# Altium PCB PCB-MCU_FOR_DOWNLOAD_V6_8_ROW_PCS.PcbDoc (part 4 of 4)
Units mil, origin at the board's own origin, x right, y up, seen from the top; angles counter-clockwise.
Board outline not stored, 4 copper layers (Top, GND1, GND2, Bottom), stack 35.4 mil thick; 280 components, 38 nets, 1144 pads, 944 vias.
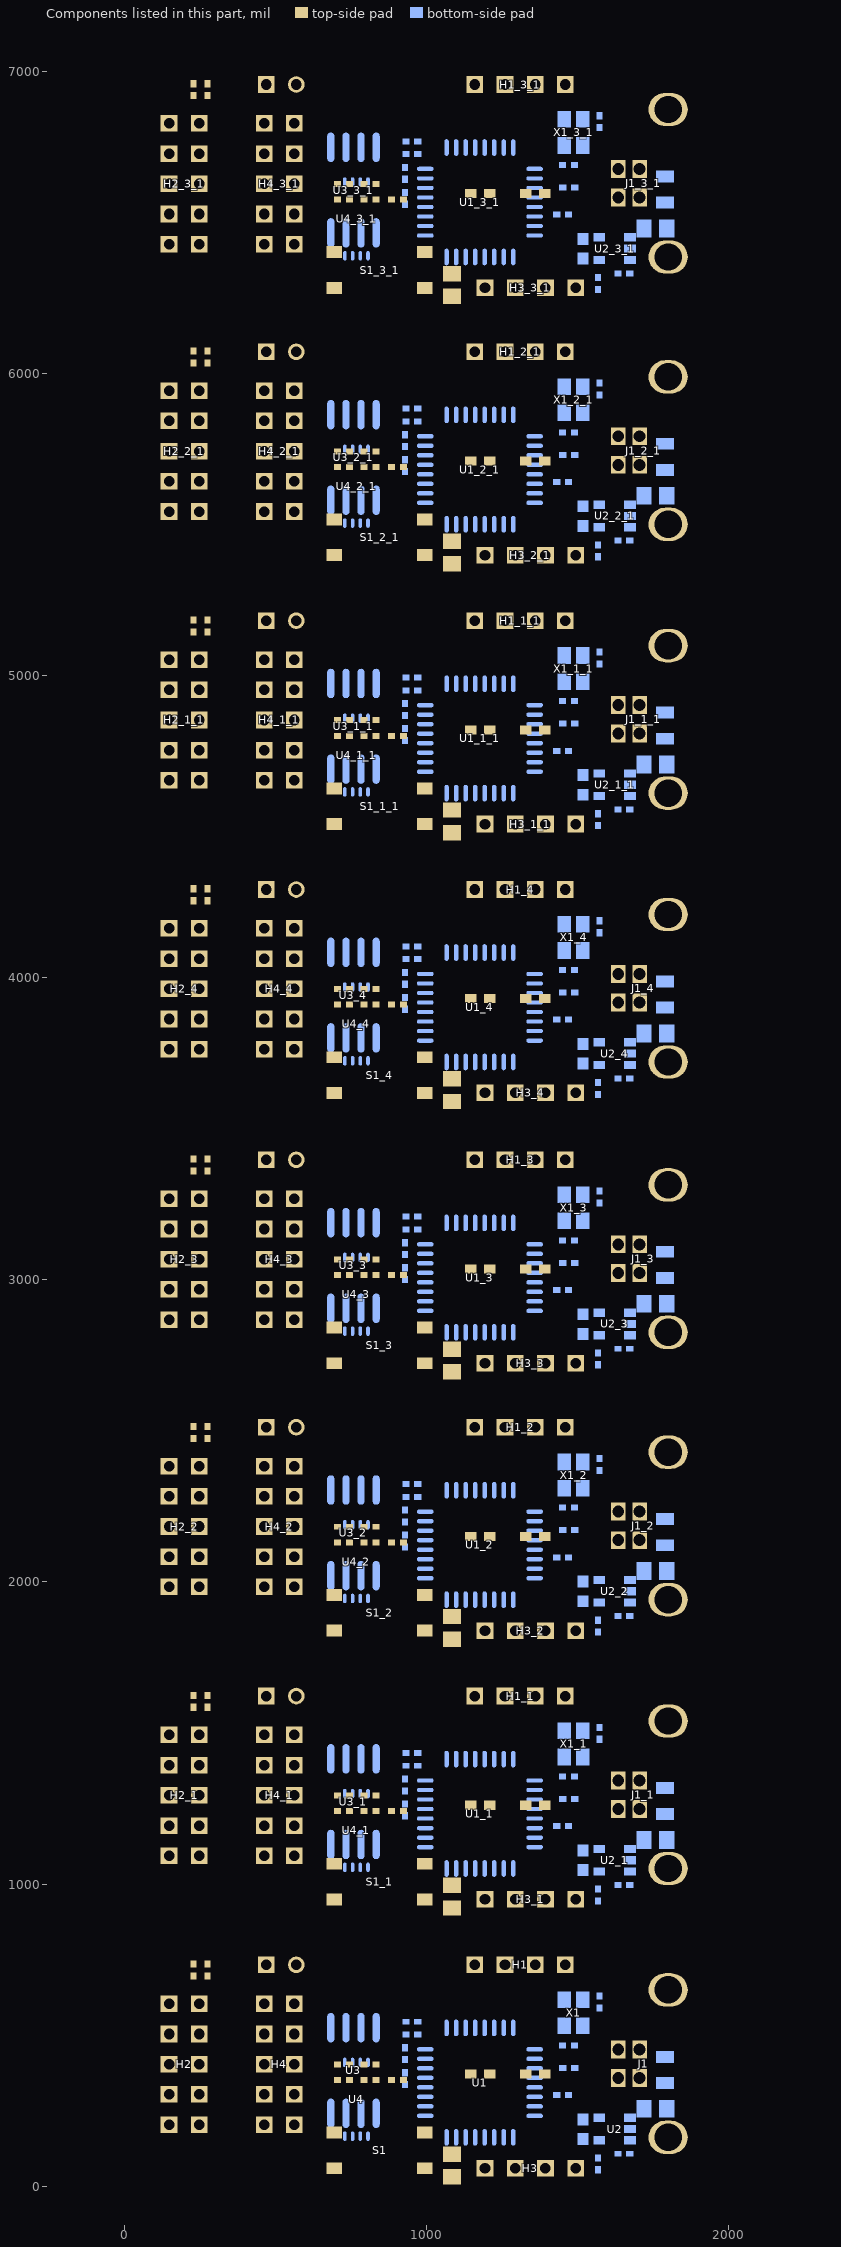
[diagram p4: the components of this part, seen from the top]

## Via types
v1: diameter 16/16/16/16 (per signal layer), hole 8, Top to Bottom, 936 vias
v2: diameter 55/55/55/55 (per signal layer), hole 37, Top to Bottom, 8 vias

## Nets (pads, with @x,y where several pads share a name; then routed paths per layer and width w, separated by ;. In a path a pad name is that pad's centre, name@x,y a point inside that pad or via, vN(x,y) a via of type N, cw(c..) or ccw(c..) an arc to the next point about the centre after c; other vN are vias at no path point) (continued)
copper on no net: (continued)
  other v1: 1723.62,917.17 1066.93,927.4 633.86,933.31 87.4,936.85 293.7,940 222.83,940.79 830.71,941.18 512.2,943.15 891.73,943.15 338.19,945.12 440.16,944.72 605.51,946.3 387.8,947.09 1934.25,949.45 61.81,958.11 772.83,957.72 1718.5,958.11 1917.32,1063.23 1896.46,1112.83 1261.81,1143.94 31.5,1189.21 403.54,1202.99 1909.45,1210.87 1120.08,1226.61 651.97,1235.28 118.11,1242.36 366.54,1249.84 297.24,1285.67 608.27,1291.18 1070.87,1307.32 1141.73,1309.29 1196.85,1327.01 685.04,1332.91 1913.39,1348.66 616.14,1380.16 25.2,1399.45 354.33,1403.78 1009.84,1407.72 1840.55,1415.59 1336.61,1417.56 1393.31,1419.53 1584.65,1425.43 1907.48,1441.18 1631.89,1458.9 1738.19,1464.8 1244.09,1478.58 874.02,1480.55 307.09,1482.52 1362.2,1492.36 1307.09,1496.3 1047.24,1510.08 991.34,1541.18 192.91,1541.57 1661.42,1553.39 572.83,1559.29 490.16,1561.26 1539.37,1578.98 419.29,1586.46 27.56,1587.64 371.26,1591.97 145.67,1611.65 337.4,1615.59 1098.82,1620.31 649.61,1623.07 921.26,1625.04 1635.83,1626.22 1742.13,1626.22 1909.45,1626.22 1828.74,1628.19 527.56,1668.35 761.81,1673.46 982.28,1673.86 1383.86,1673.46 1771.65,1673.46 1236.22,1677.4 1723.62,1807.17 1066.93,1817.4 633.86,1823.31 87.4,1826.85 293.7,1830 222.83,1830.79 830.71,1831.18 512.2,1833.15 891.73,1833.15 338.19,1835.12 440.16,1834.72 605.51,1836.3 387.8,1837.09 1934.25,1839.45 61.81,1848.11 772.83,1847.72 1718.5,1848.11 1917.32,1953.23 1896.46,2002.83 1261.81,2033.94 31.5,2079.21 403.54,2092.99 1909.45,2100.87 1120.08,2116.61 651.97,2125.28 118.11,2132.36 366.54,2139.84 297.24,2175.67 608.27,2181.18 1070.87,2197.32 1141.73,2199.29 1196.85,2217.01 685.04,2222.91 1913.39,2238.66 616.14,2270.16 25.2,2289.45 354.33,2293.78 1009.84,2297.72 1840.55,2305.59 1336.61,2307.56 1393.31,2309.53 1584.65,2315.43 1907.48,2331.18 1631.89,2348.9 1738.19,2354.8 1244.09,2368.58 874.02,2370.55 307.09,2372.52 1362.2,2382.36 1307.09,2386.3 1047.24,2400.08 991.34,2431.18 192.91,2431.57 1661.42,2443.39 572.83,2449.29 490.16,2451.26 1539.37,2468.98 419.29,2476.46 27.56,2477.64 371.26,2481.97 145.67,2501.65 337.4,2505.59 1098.82,2510.31 649.61,2513.07 921.26,2515.04 1635.83,2516.22 1742.13,2516.22 1909.45,2516.22 1828.74,2518.19 527.56,2558.35 761.81,2563.46 982.28,2563.86 1383.86,2563.46 1771.65,2563.46 1236.22,2567.4 1723.62,2692.17 1066.93,2702.4 633.86,2708.31 87.4,2711.85 293.7,2715 222.83,2715.79 830.71,2716.18 512.2,2718.15 891.73,2718.15 338.19,2720.12 440.16,2719.72 605.51,2721.3 387.8,2722.09 1934.25,2724.45 61.81,2733.11 772.83,2732.72 1718.5,2733.11 1917.32,2838.23 1896.46,2887.83 1261.81,2918.94 31.5,2964.21 403.54,2977.99 1909.45,2985.87 1120.08,3001.61 651.97,3010.28 118.11,3017.36 366.54,3024.84 297.24,3060.67 608.27,3066.18 1070.87,3082.32 1141.73,3084.29 1196.85,3102.01 685.04,3107.91 1913.39,3123.66 616.14,3155.16 25.2,3174.45 354.33,3178.78 1009.84,3182.72 1840.55,3190.59 1336.61,3192.56 1393.31,3194.53 1584.65,3200.43 1907.48,3216.18 1631.89,3233.9 1738.19,3239.8 1244.09,3253.58 874.02,3255.55 307.09,3257.52 1362.2,3267.36 1307.09,3271.3 1047.24,3285.08 991.34,3316.18 192.91,3316.57 1661.42,3328.39 572.83,3334.29 490.16,3336.26 1539.37,3353.98 419.29,3361.46 27.56,3362.64 371.26,3366.97 145.67,3386.65 337.4,3390.59 1098.82,3395.31 649.61,3398.07 921.26,3400.04 1635.83,3401.22 1742.13,3401.22 1909.45,3401.22 1828.74,3403.19 527.56,3443.35 761.81,3448.46 982.28,3448.86 1383.86,3448.46 1771.65,3448.46 1236.22,3452.4 1723.62,3587.17 1066.93,3597.4 633.86,3603.31 87.4,3606.85 293.7,3610 222.83,3610.79 830.71,3611.18 512.2,3613.15 891.73,3613.15 338.19,3615.12 440.16,3614.72 605.51,3616.3 387.8,3617.09 1934.25,3619.45 61.81,3628.11 772.83,3627.72 1718.5,3628.11 1917.32,3733.23 1896.46,3782.83 1261.81,3813.94 31.5,3859.21 403.54,3872.99 1909.45,3880.87 1120.08,3896.61 651.97,3905.28 118.11,3912.36 366.54,3919.84 297.24,3955.67 608.27,3961.18 1070.87,3977.32 1141.73,3979.29 1196.85,3997.01 685.04,4002.91 1913.39,4018.66 616.14,4050.16 25.2,4069.45 354.33,4073.78 1009.84,4077.72 1840.55,4085.59 1336.61,4087.56 1393.31,4089.53 1584.65,4095.43 1907.48,4111.18 1631.89,4128.9 1738.19,4134.8 1244.09,4148.58 874.02,4150.55 307.09,4152.52 1362.2,4162.36 1307.09,4166.3 1047.24,4180.08 991.34,4211.18 192.91,4211.57 1661.42,4223.39 572.83,4229.29 490.16,4231.26 1539.37,4248.98 419.29,4256.46 27.56,4257.64 371.26,4261.97 145.67,4281.65 337.4,4285.59 1098.82,4290.31 649.61,4293.07 921.26,4295.04 1635.83,4296.22 1742.13,4296.22 1909.45,4296.22 1828.74,4298.19 527.56,4338.35 761.81,4343.46 982.28,4343.86 1383.86,4343.46 1771.65,4343.46 1236.22,4347.4 1723.62,4477.17 1066.93,4487.4 633.86,4493.31 87.4,4496.85 293.7,4500 222.83,4500.79 830.71,4501.18 512.2,4503.15 891.73,4503.15 338.19,4505.12 440.16,4504.72 605.51,4506.3 387.8,4507.09 1934.25,4509.45 61.81,4518.11 772.83,4517.72 1718.5,4518.11 1917.32,4623.23 1896.46,4672.83 1261.81,4703.94 31.5,4749.21 403.54,4762.99 1909.45,4770.87 1120.08,4786.61 651.97,4795.28 118.11,4802.36 366.54,4809.84 297.24,4845.67 608.27,4851.18 1070.87,4867.32 1141.73,4869.29 1196.85,4887.01 685.04,4892.91 1913.39,4908.66 616.14,4940.16 25.2,4959.45 354.33,4963.78 1009.84,4967.72 1840.55,4975.59 1336.61,4977.56 1393.31,4979.53 1584.65,4985.43 1907.48,5001.18 1631.89,5018.9 1738.19,5024.8 1244.09,5038.58 874.02,5040.55 307.09,5042.52 1362.2,5052.36 1307.09,5056.3 1047.24,5070.08 991.34,5101.18 192.91,5101.57 1661.42,5113.39 572.83,5119.29 490.16,5121.26 1539.37,5138.98 419.29,5146.46 27.56,5147.64 371.26,5151.97 145.67,5171.65 337.4,5175.59 1098.82,5180.31 649.61,5183.07 921.26,5185.04 1635.83,5186.22 1742.13,5186.22 1909.45,5186.22 1828.74,5188.19 527.56,5228.35 761.81,5233.46 982.28,5233.86 1383.86,5233.46 1771.65,5233.46 1236.22,5237.4 1723.62,5367.17 1066.93,5377.4 633.86,5383.31 87.4,5386.85 293.7,5390 222.83,5390.79 830.71,5391.18 512.2,5393.15 891.73,5393.15 338.19,5395.12 440.16,5394.72 605.51,5396.3 387.8,5397.09 1934.25,5399.45 61.81,5408.11 772.83,5407.72 1718.5,5408.11 1917.32,5513.23 1896.46,5562.83 1261.81,5593.94 31.5,5639.21 403.54,5652.99 1909.45,5660.87 1120.08,5676.61 651.97,5685.28 118.11,5692.36 366.54,5699.84 297.24,5735.67 608.27,5741.18 1070.87,5757.32 1141.73,5759.29 1196.85,5777.01 685.04,5782.91 1913.39,5798.66 616.14,5830.16 25.2,5849.45 354.33,5853.78 1009.84,5857.72 1840.55,5865.59 1336.61,5867.56 1393.31,5869.53 1584.65,5875.43 1907.48,5891.18 1631.89,5908.9 1738.19,5914.8 1244.09,5928.58 874.02,5930.55 307.09,5932.52 1362.2,5942.36 1307.09,5946.3 1047.24,5960.08 991.34,5991.18 192.91,5991.57 1661.42,6003.39 572.83,6009.29 490.16,6011.26 1539.37,6028.98 419.29,6036.46 27.56,6037.64 371.26,6041.97 145.67,6061.65 337.4,6065.59 1098.82,6070.31 649.61,6073.07 921.26,6075.04 1635.83,6076.22 1742.13,6076.22 1909.45,6076.22 1828.74,6078.19 527.56,6118.35 761.81,6123.46 982.28,6123.86 1383.86,6123.46 1771.65,6123.46 1236.22,6127.4 1723.62,6252.17 1066.93,6262.4 633.86,6268.31 87.4,6271.85 293.7,6275 222.83,6275.79 830.71,6276.18 512.2,6278.15 891.73,6278.15 338.19,6280.12 440.16,6279.72 605.51,6281.3 387.8,6282.09 1934.25,6284.45 61.81,6293.11 772.83,6292.72 1718.5,6293.11 1917.32,6398.23 1896.46,6447.83 1261.81,6478.94 31.5,6524.21 403.54,6537.99 1909.45,6545.87 1120.08,6561.61 651.97,6570.28 118.11,6577.36 366.54,6584.84 297.24,6620.67 608.27,6626.18 1070.87,6642.32 1141.73,6644.29 1196.85,6662.01 685.04,6667.91 1913.39,6683.66 616.14,6715.16 25.2,6734.45 354.33,6738.78 1009.84,6742.72 1840.55,6750.59 1336.61,6752.56 1393.31,6754.53 1584.65,6760.43 1907.48,6776.18 1631.89,6793.9 1738.19,6799.8 1244.09,6813.58 874.02,6815.55 307.09,6817.52 1362.2,6827.36 1307.09,6831.3 1047.24,6845.08 991.34,6876.18 192.91,6876.57 1661.42,6888.39 572.83,6894.29 490.16,6896.26 1539.37,6913.98 419.29,6921.46 27.56,6922.64 371.26,6926.97 145.67,6946.65 337.4,6950.59 1098.82,6955.31 649.61,6958.07 921.26,6960.04 1635.83,6961.22 1742.13,6961.22 1909.45,6961.22 1828.74,6963.19 527.56,7003.35 761.81,7008.46 982.28,7008.86 1383.86,7008.46 1771.65,7008.46 1236.22,7012.4

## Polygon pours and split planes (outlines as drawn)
no net on Top "Top-GGND" (solid, remove dead copper, pour order 12): -3.15,3560 2215,3560 2215,4378.5 -3.15,4378.5
no net on Top "Top-GGND" (solid, remove dead copper, pour order 11): -3.15,4450 2215,4450 2215,5268.5 -3.15,5268.5
no net on Top "Top-GGND" (solid, remove dead copper, pour order 10): -3.15,5340 2215,5340 2215,6158.5 -3.15,6158.5
no net on Top "Top-GGND" (solid, remove dead copper, pour order 9): -3.15,6225 2215,6225 2215,7043.5 -3.15,7043.5
no net on Top "Top-GGND" (solid, remove dead copper, pour order 9): -3.15,2665 2215,2665 2215,3483.5 -3.15,3483.5
no net on Top "Top-GGND" (solid, remove dead copper, pour order 10): -3.15,1780 2215,1780 2215,2598.5 -3.15,2598.5
no net on Top "Top-GGND" (solid, remove dead copper, pour order 11): -3.15,890 2215,890 2215,1708.5 -3.15,1708.5
GGND on Top "Top-GGND" (solid, remove dead copper, pour order 12): -3.15,0 2215,0 2215,818.5 -3.15,818.5
no net on Bottom "Bottom-GGND" (solid, remove dead copper, pour order 16): -6.69,3560 2210,3560 2210,4370.24 -6.69,4370.24
no net on Bottom "Bottom-GGND" (solid, remove dead copper, pour order 15): -6.69,4450 2210,4450 2210,5260.24 -6.69,5260.24
no net on Bottom "Bottom-GGND" (solid, remove dead copper, pour order 14): -6.69,5340 2210,5340 2210,6150.24 -6.69,6150.24
no net on Bottom "Bottom-GGND" (solid, remove dead copper, pour order 13): -6.69,6225 2210,6225 2210,7035.24 -6.69,7035.24
no net on Bottom "Bottom-GGND" (solid, remove dead copper, pour order 13): -6.69,2665 2210,2665 2210,3475.24 -6.69,3475.24
no net on Bottom "Bottom-GGND" (solid, remove dead copper, pour order 14): -6.69,1780 2210,1780 2210,2590.24 -6.69,2590.24
no net on Bottom "Bottom-GGND" (solid, remove dead copper, pour order 15): -6.69,890 2210,890 2210,1700.24 -6.69,1700.24
GGND on Bottom "Bottom-GGND" (solid, remove dead copper, pour order 16): -6.69,0 2210,0 2210,810.24 -6.69,810.24

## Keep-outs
Keep-Out Layer:
  lines w10: 0,59.01 ccw(c56.63,56.63) 59.1,0 ; 0,59.01 0,325 -55,325 -135,325 -135,3143.54 -135,6703.54 -55,6703.54 0,6703.54 0,6973.03 cw(c57.94,6974.14) 59.06,7032.09 2160,7032.09 cw(c2157.3,6970.34) 2219.06,6973.03 2219.06,6284.06 cw(c2159.85,6284.26) 2159.95,6225.05 ; 0,748.03 cw(c57.94,749.14) 59.06,807.09 2160,807.09 cw(c2157.3,745.34) 2219.06,748.03 2219.06,59.06 cw(c2159.85,59.26) 2159.95,0.05 ; 0,750 0,475 -55,475 -55,1218.54 0,1218.54 0,949.01 ; 0,949.01 ccw(c56.63,946.63) 59.1,890 ; 0,1839.01 ccw(c56.63,1836.63) 59.1,1780 ; 0,1839.01 0,2108.54 -55,2108.54 -55,1368.54 0,1368.54 0,1638.03 cw(c57.94,1639.14) 59.06,1697.09 2160,1697.09 cw(c2157.3,1635.34) 2219.06,1638.03 2219.06,949.06 cw(c2159.85,949.26) 2159.95,890.05 ; 0,2724.01 ccw(c56.63,2721.63) 59.1,2665 ; 0,2724.01 0,2993.54 -55,2993.54 -55,2258.54 0,2258.54 0,2528.03 cw(c57.94,2529.14) 59.06,2587.09 2160,2587.09 cw(c2157.3,2525.34) 2219.06,2528.03 2219.06,1839.06 cw(c2159.85,1839.26) 2159.95,1780.05 ; 0,3619.01 ccw(c56.63,3616.63) 59.1,3560 ; 0,3619.01 0,3885 -55,3885 -55,3143.54 0,3143.54 0,3413.03 cw(c57.94,3414.14) 59.06,3472.09 2160,3472.09 cw(c2157.3,3410.34) 2219.06,3413.03 2219.06,2724.06 cw(c2159.85,2724.26) 2159.95,2665.05 ; 0,4308.03 cw(c57.94,4309.14) 59.06,4367.09 2160,4367.09 cw(c2157.3,4305.34) 2219.06,4308.03 2219.06,3619.06 cw(c2159.85,3619.26) 2159.95,3560.05 ; 0,4310 0,4035 -55,4035 -55,4778.54 0,4778.54 0,4509.01 ; 0,4509.01 ccw(c56.63,4506.63) 59.1,4450 ; 0,5399.01 ccw(c56.63,5396.63) 59.1,5340 ; 0,5399.01 0,5668.54 -55,5668.54 -55,4928.54 0,4928.54 0,5198.03 cw(c57.94,5199.14) 59.06,5257.09 2160,5257.09 cw(c2157.3,5195.34) 2219.06,5198.03 2219.06,4509.06 cw(c2159.85,4509.26) 2159.95,4450.05 ; 0,6284.01 ccw(c56.63,6281.63) 59.1,6225 ; 0,6284.01 0,6553.54 -55,6553.54 -55,5818.54 0,5818.54 0,6088.03 cw(c57.94,6089.14) 59.06,6147.09 2160,6147.09 cw(c2157.3,6085.34) 2219.06,6088.03 2219.06,5399.06 cw(c2159.85,5399.26) 2159.95,5340.05 ; 59.06,0 2160,0 ; 59.06,890 2160,890 ; 59.06,1780 2160,1780 ; 59.06,2665 2160,2665 ; 59.06,3560 2160,3560 ; 59.06,4450 2160,4450 ; 59.06,5340 2160,5340 ; 59.06,6225 2160,6225

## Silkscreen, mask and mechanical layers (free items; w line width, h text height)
Silkscreen Top:
  drawing of 232 lines, arcs and shapes, not listed
  text "VDD" at 627.95,6971.06 h25.59
  text "VCC" at 330.31,6969.09 h25.59
  text "深圳市集贤科技有限公司" at 1613.78,6967.52 h50
  text "1.0" at 1229.53,6841.54 h29.53
  text "0.7" at 1326.38,6841.93 h29.53
  text "1.1" at 1132.28,6840.75 h29.53
  text "0.6" at 1427.95,6840.75 h29.53
  text "WP" at 348.43,6804.92 h25.59 r90
  text "CS" at 405.91,6801.38 h25.59 r90
  text "CS" at 89.37,6799.02 h25.59 r90
  text "WP" at 657.09,6792.72 h25.59 r90
  text "HW SPI Jumpers" at 681.89,6773.82 h29.53
  text "Int:R7=R8=0R" at 704.33,6705.71 h29.53
  text "VPP" at 87.8,6699.8 h25.59 r90
  text "VPP" at 412.2,6697.05 h25.59 r90
  text "VCC" at 347.24,6693.11 h25.59 r90
  text "VCC" at 655.91,6680.91 h25.59 r90
  text "GND" at 89.37,6592.72 h25.59 r90
  text "GND" at 343.31,6591.54 h25.59 r90
  text "GND" at 405.51,6588.78 h25.59 r90
  text "GND" at 651.97,6579.33 h25.59 r90
  text "P2.4" at 88.58,6489.57 h25.59 r90
  text "P2.3" at 343.31,6487.2 h25.59 r90
  text "Ext:R9=R10=R13=0R" at 665.35,6478.15 h25.59
  text "POWER" at 1270.47,6440.75 h39.37
  text "MISO" at 649.21,6383.66 h25.59 r90
  text "MOSI" at 90.55,6379.33 h25.59 r90
  text "MISO" at 342.52,6377.36 h25.59 r90
  text "MOSI" at 406.69,6375.39 h25.59 r90
  text "VDD" at 1130.71,6345.47 h29.53
  text "C2D" at 1230.71,6346.26 h29.53
  text "CK" at 1374.41,6343.5 h29.53
  text "GND" at 1445.67,6344.29 h29.53
  text "SW" at 188.19,6265.16 h49.21 r90
  text "HW" at 505.51,6260.43 h49.21 r90
  text "SPI" at 269.29,6258.46 h49.21 r90
  text "MCU_FOR_DOWMLOAD_v1.0" at 1627.17,6254.92 h29.53
  text "SPI" at 590.16,6253.74 h49.21 r90
  text "VDD" at 627.95,6086.06 h25.59
  text "VCC" at 330.31,6084.09 h25.59
  text "深圳市集贤科技有限公司" at 1613.78,6082.52 h50
  text "1.0" at 1229.53,5956.54 h29.53
  text "0.7" at 1326.38,5956.93 h29.53
  text "1.1" at 1132.28,5955.75 h29.53
  text "0.6" at 1427.95,5955.75 h29.53
  text "WP" at 348.43,5919.92 h25.59 r90
  text "CS" at 405.91,5916.38 h25.59 r90
  text "CS" at 89.37,5914.02 h25.59 r90
  text "WP" at 657.09,5907.72 h25.59 r90
  text "HW SPI Jumpers" at 681.89,5888.82 h29.53
  text "Int:R7=R8=0R" at 704.33,5820.71 h29.53
  text "VPP" at 87.8,5814.8 h25.59 r90
  text "VPP" at 412.2,5812.05 h25.59 r90
  text "VCC" at 347.24,5808.11 h25.59 r90
  text "VCC" at 655.91,5795.91 h25.59 r90
  text "GND" at 89.37,5707.72 h25.59 r90
  text "GND" at 343.31,5706.54 h25.59 r90
  text "GND" at 405.51,5703.78 h25.59 r90
  text "GND" at 651.97,5694.33 h25.59 r90
  text "P2.4" at 88.58,5604.57 h25.59 r90
  text "P2.3" at 343.31,5602.2 h25.59 r90
  text "Ext:R9=R10=R13=0R" at 665.35,5593.15 h25.59
  text "POWER" at 1270.47,5555.75 h39.37
  text "MISO" at 649.21,5498.66 h25.59 r90
  text "MOSI" at 90.55,5494.33 h25.59 r90
  text "MISO" at 342.52,5492.36 h25.59 r90
  text "MOSI" at 406.69,5490.39 h25.59 r90
  text "VDD" at 1130.71,5460.47 h29.53
  text "C2D" at 1230.71,5461.26 h29.53
  text "CK" at 1374.41,5458.5 h29.53
  text "GND" at 1445.67,5459.29 h29.53
  text "SW" at 188.19,5380.16 h49.21 r90
  text "HW" at 505.51,5375.43 h49.21 r90
  text "SPI" at 269.29,5373.46 h49.21 r90
  text "MCU_FOR_DOWMLOAD_v1.0" at 1627.17,5369.92 h29.53
  text "SPI" at 590.16,5368.74 h49.21 r90
  text "VDD" at 627.95,5196.06 h25.59
  text "VCC" at 330.31,5194.09 h25.59
  text "深圳市集贤科技有限公司" at 1613.78,5192.52 h50
  text "1.0" at 1229.53,5066.54 h29.53
  text "0.7" at 1326.38,5066.93 h29.53
  text "1.1" at 1132.28,5065.75 h29.53
  text "0.6" at 1427.95,5065.75 h29.53
  text "WP" at 348.43,5029.92 h25.59 r90
  text "CS" at 405.91,5026.38 h25.59 r90
  text "CS" at 89.37,5024.02 h25.59 r90
  text "WP" at 657.09,5017.72 h25.59 r90
  text "HW SPI Jumpers" at 681.89,4998.82 h29.53
  text "Int:R7=R8=0R" at 704.33,4930.71 h29.53
  text "VPP" at 87.8,4924.8 h25.59 r90
  text "VPP" at 412.2,4922.05 h25.59 r90
  text "VCC" at 347.24,4918.11 h25.59 r90
  text "VCC" at 655.91,4905.91 h25.59 r90
  text "GND" at 89.37,4817.72 h25.59 r90
  text "GND" at 343.31,4816.54 h25.59 r90
  text "GND" at 405.51,4813.78 h25.59 r90
  text "GND" at 651.97,4804.33 h25.59 r90
  text "P2.4" at 88.58,4714.57 h25.59 r90
  text "P2.3" at 343.31,4712.2 h25.59 r90
  text "Ext:R9=R10=R13=0R" at 665.35,4703.15 h25.59
  text "POWER" at 1270.47,4665.75 h39.37
  text "MISO" at 649.21,4608.66 h25.59 r90
  text "MOSI" at 90.55,4604.33 h25.59 r90
  text "MISO" at 342.52,4602.36 h25.59 r90
  text "MOSI" at 406.69,4600.39 h25.59 r90
  text "VDD" at 1130.71,4570.47 h29.53
  text "C2D" at 1230.71,4571.26 h29.53
  text "CK" at 1374.41,4568.5 h29.53
  text "GND" at 1445.67,4569.29 h29.53
  text "SW" at 188.19,4490.16 h49.21 r90
  text "HW" at 505.51,4485.43 h49.21 r90
  text "SPI" at 269.29,4483.46 h49.21 r90
  text "MCU_FOR_DOWMLOAD_v1.0" at 1627.17,4479.92 h29.53
  text "SPI" at 590.16,4478.74 h49.21 r90
  text "VDD" at 627.95,4306.06 h25.59
  text "VCC" at 330.31,4304.09 h25.59
  text "深圳市集贤科技有限公司" at 1613.78,4302.52 h50
  text "1.0" at 1229.53,4176.54 h29.53
  text "0.7" at 1326.38,4176.93 h29.53
  text "1.1" at 1132.28,4175.75 h29.53
  text "0.6" at 1427.95,4175.75 h29.53
  text "WP" at 348.43,4139.92 h25.59 r90
  text "CS" at 405.91,4136.38 h25.59 r90
  text "CS" at 89.37,4134.02 h25.59 r90
  text "WP" at 657.09,4127.72 h25.59 r90
  text "HW SPI Jumpers" at 681.89,4108.82 h29.53
  text "Int:R7=R8=0R" at 704.33,4040.71 h29.53
  text "VPP" at 87.8,4034.8 h25.59 r90
  text "VPP" at 412.2,4032.05 h25.59 r90
  text "VCC" at 347.24,4028.11 h25.59 r90
  text "VCC" at 655.91,4015.91 h25.59 r90
  text "GND" at 89.37,3927.72 h25.59 r90
  text "GND" at 343.31,3926.54 h25.59 r90
  text "GND" at 405.51,3923.78 h25.59 r90
  text "GND" at 651.97,3914.33 h25.59 r90
  text "P2.4" at 88.58,3824.57 h25.59 r90
  text "P2.3" at 343.31,3822.2 h25.59 r90
  text "Ext:R9=R10=R13=0R" at 665.35,3813.15 h25.59
  text "POWER" at 1270.47,3775.75 h39.37
  text "MISO" at 649.21,3718.66 h25.59 r90
  text "MOSI" at 90.55,3714.33 h25.59 r90
  text "MISO" at 342.52,3712.36 h25.59 r90
  text "MOSI" at 406.69,3710.39 h25.59 r90
  text "VDD" at 1130.71,3680.47 h29.53
  text "C2D" at 1230.71,3681.26 h29.53
  text "CK" at 1374.41,3678.5 h29.53
  text "GND" at 1445.67,3679.29 h29.53
  text "SW" at 188.19,3600.16 h49.21 r90
  text "HW" at 505.51,3595.43 h49.21 r90
  text "SPI" at 269.29,3593.46 h49.21 r90
  text "MCU_FOR_DOWMLOAD_v1.0" at 1627.17,3589.92 h29.53
  text "SPI" at 590.16,3588.74 h49.21 r90
  text "VDD" at 627.95,3411.06 h25.59
  text "VCC" at 330.31,3409.09 h25.59
  text "深圳市集贤科技有限公司" at 1613.78,3407.52 h50
  text "1.0" at 1229.53,3281.54 h29.53
  text "0.7" at 1326.38,3281.93 h29.53
  text "1.1" at 1132.28,3280.75 h29.53
  text "0.6" at 1427.95,3280.75 h29.53
  text "WP" at 348.43,3244.92 h25.59 r90
  text "CS" at 405.91,3241.38 h25.59 r90
  text "CS" at 89.37,3239.02 h25.59 r90
  text "WP" at 657.09,3232.72 h25.59 r90
  text "HW SPI Jumpers" at 681.89,3213.82 h29.53
  text "Int:R7=R8=0R" at 704.33,3145.71 h29.53
  text "VPP" at 87.8,3139.8 h25.59 r90
  text "VPP" at 412.2,3137.05 h25.59 r90
  text "VCC" at 347.24,3133.11 h25.59 r90
  text "VCC" at 655.91,3120.91 h25.59 r90
  text "GND" at 89.37,3032.72 h25.59 r90
  text "GND" at 343.31,3031.54 h25.59 r90
  text "GND" at 405.51,3028.78 h25.59 r90
  text "GND" at 651.97,3019.33 h25.59 r90
  text "P2.4" at 88.58,2929.57 h25.59 r90
  text "P2.3" at 343.31,2927.2 h25.59 r90
  text "Ext:R9=R10=R13=0R" at 665.35,2918.15 h25.59
  text "POWER" at 1270.47,2880.75 h39.37
  text "MISO" at 649.21,2823.66 h25.59 r90
  text "MOSI" at 90.55,2819.33 h25.59 r90
  text "MISO" at 342.52,2817.36 h25.59 r90
  text "MOSI" at 406.69,2815.39 h25.59 r90
  text "VDD" at 1130.71,2785.47 h29.53
  text "C2D" at 1230.71,2786.26 h29.53
  text "CK" at 1374.41,2783.5 h29.53
  text "GND" at 1445.67,2784.29 h29.53
  text "SW" at 188.19,2705.16 h49.21 r90
  text "HW" at 505.51,2700.43 h49.21 r90
  text "SPI" at 269.29,2698.46 h49.21 r90
  text "MCU_FOR_DOWMLOAD_v1.0" at 1627.17,2694.92 h29.53
  text "SPI" at 590.16,2693.74 h49.21 r90
  text "VDD" at 627.95,2526.06 h25.59
  text "VCC" at 330.31,2524.09 h25.59
  text "深圳市集贤科技有限公司" at 1613.78,2522.52 h50
  text "1.0" at 1229.53,2396.54 h29.53
  text "0.7" at 1326.38,2396.93 h29.53
  text "1.1" at 1132.28,2395.75 h29.53
  text "0.6" at 1427.95,2395.75 h29.53
  text "WP" at 348.43,2359.92 h25.59 r90
  text "CS" at 405.91,2356.38 h25.59 r90
  text "CS" at 89.37,2354.02 h25.59 r90
  text "WP" at 657.09,2347.72 h25.59 r90
  text "HW SPI Jumpers" at 681.89,2328.82 h29.53
  text "Int:R7=R8=0R" at 704.33,2260.71 h29.53
  text "VPP" at 87.8,2254.8 h25.59 r90
  text "VPP" at 412.2,2252.05 h25.59 r90
  text "VCC" at 347.24,2248.11 h25.59 r90
  text "VCC" at 655.91,2235.91 h25.59 r90
  text "GND" at 89.37,2147.72 h25.59 r90
  text "GND" at 343.31,2146.54 h25.59 r90
  text "GND" at 405.51,2143.78 h25.59 r90
  text "GND" at 651.97,2134.33 h25.59 r90
  text "P2.4" at 88.58,2044.57 h25.59 r90
  text "P2.3" at 343.31,2042.2 h25.59 r90
  text "Ext:R9=R10=R13=0R" at 665.35,2033.15 h25.59
  text "POWER" at 1270.47,1995.75 h39.37
  text "MISO" at 649.21,1938.66 h25.59 r90
  text "MOSI" at 90.55,1934.33 h25.59 r90
  text "MISO" at 342.52,1932.36 h25.59 r90
  text "MOSI" at 406.69,1930.39 h25.59 r90
  text "VDD" at 1130.71,1900.47 h29.53
  text "C2D" at 1230.71,1901.26 h29.53
  text "CK" at 1374.41,1898.5 h29.53
  text "GND" at 1445.67,1899.29 h29.53
  text "SW" at 188.19,1820.16 h49.21 r90
  text "HW" at 505.51,1815.43 h49.21 r90
  text "SPI" at 269.29,1813.46 h49.21 r90
  text "MCU_FOR_DOWMLOAD_v1.0" at 1627.17,1809.92 h29.53
  text "SPI" at 590.16,1808.74 h49.21 r90
  text "VDD" at 627.95,1636.06 h25.59
  text "VCC" at 330.31,1634.09 h25.59
  text "深圳市集贤科技有限公司" at 1613.78,1632.52 h50
  text "1.0" at 1229.53,1506.54 h29.53
  text "0.7" at 1326.38,1506.93 h29.53
  text "1.1" at 1132.28,1505.75 h29.53
  text "0.6" at 1427.95,1505.75 h29.53
  text "WP" at 348.43,1469.92 h25.59 r90
  text "CS" at 405.91,1466.38 h25.59 r90
  text "CS" at 89.37,1464.02 h25.59 r90
  text "WP" at 657.09,1457.72 h25.59 r90
  text "HW SPI Jumpers" at 681.89,1438.82 h29.53
  text "Int:R7=R8=0R" at 704.33,1370.71 h29.53
  text "VPP" at 87.8,1364.8 h25.59 r90
  text "VPP" at 412.2,1362.05 h25.59 r90
  text "VCC" at 347.24,1358.11 h25.59 r90
  text "VCC" at 655.91,1345.91 h25.59 r90
  text "GND" at 89.37,1257.72 h25.59 r90
  text "GND" at 343.31,1256.54 h25.59 r90
  text "GND" at 405.51,1253.78 h25.59 r90
  text "GND" at 651.97,1244.33 h25.59 r90
  text "P2.4" at 88.58,1154.57 h25.59 r90
  text "P2.3" at 343.31,1152.2 h25.59 r90
  text "Ext:R9=R10=R13=0R" at 665.35,1143.15 h25.59
  text "POWER" at 1270.47,1105.75 h39.37
  text "MISO" at 649.21,1048.66 h25.59 r90
  text "MOSI" at 90.55,1044.33 h25.59 r90
  text "MISO" at 342.52,1042.36 h25.59 r90
  text "MOSI" at 406.69,1040.39 h25.59 r90
  text "VDD" at 1130.71,1010.47 h29.53
  text "C2D" at 1230.71,1011.26 h29.53
  text "CK" at 1374.41,1008.5 h29.53
  text "GND" at 1445.67,1009.29 h29.53
  text "SW" at 188.19,930.16 h49.21 r90
  text "HW" at 505.51,925.43 h49.21 r90
  text "SPI" at 269.29,923.46 h49.21 r90
  text "MCU_FOR_DOWMLOAD_v1.0" at 1627.17,919.92 h29.53
  text "SPI" at 590.16,918.74 h49.21 r90
  text "VDD" at 627.95,746.06 h25.59
  text "VCC" at 330.31,744.09 h25.59
  text "深圳市集贤科技有限公司" at 1613.78,742.52 h50
  text "1.0" at 1229.53,616.54 h29.53
  text "0.7" at 1326.38,616.93 h29.53
  text "1.1" at 1132.28,615.75 h29.53
  text "0.6" at 1427.95,615.75 h29.53
  text "WP" at 348.43,579.92 h25.59 r90
  text "CS" at 405.91,576.38 h25.59 r90
  text "CS" at 89.37,574.02 h25.59 r90
  text "WP" at 657.09,567.72 h25.59 r90
  text "HW SPI Jumpers" at 681.89,548.82 h29.53
  text "Int:R7=R8=0R" at 704.33,480.71 h29.53
  text "VPP" at 87.8,474.8 h25.59 r90
  text "VPP" at 412.2,472.05 h25.59 r90
  text "VCC" at 347.24,468.11 h25.59 r90
  text "VCC" at 655.91,455.91 h25.59 r90
  text "GND" at 89.37,367.72 h25.59 r90
  text "GND" at 343.31,366.54 h25.59 r90
  text "GND" at 405.51,363.78 h25.59 r90
  text "GND" at 651.97,354.33 h25.59 r90
  text "P2.4" at 88.58,264.57 h25.59 r90
  text "P2.3" at 343.31,262.2 h25.59 r90
  text "Ext:R9=R10=R13=0R" at 665.35,253.15 h25.59
  text "POWER" at 1270.47,215.75 h39.37
  text "MISO" at 649.21,158.66 h25.59 r90
  text "MOSI" at 90.55,154.33 h25.59 r90
  text "MISO" at 342.52,152.36 h25.59 r90
  text "MOSI" at 406.69,150.39 h25.59 r90
  text "VDD" at 1130.71,120.47 h29.53
  text "C2D" at 1230.71,121.26 h29.53
  text "CK" at 1374.41,118.5 h29.53
  text "GND" at 1445.67,119.29 h29.53
  text "SW" at 188.19,40.16 h49.21 r90
  text "HW" at 505.51,35.43 h49.21 r90
  text "SPI" at 269.29,33.46 h49.21 r90
  text "MCU_FOR_DOWMLOAD_v1.0" at 1627.17,29.92 h29.53
  text "SPI" at 590.16,28.74 h49.21 r90
Silkscreen Bottom:
  lines w11.81: 103.4,156.3 290.7,156.3 290.7,654.72 103.4,654.72 103.4,156.3 ; 103.4,1046.3 103.4,1544.72 290.7,1544.72 290.7,1046.3 103.4,1046.3 ; 103.4,1936.3 103.4,2434.72 290.7,2434.72 290.7,1936.3 103.4,1936.3 ; 103.4,2821.3 103.4,3319.72 290.7,3319.72 290.7,2821.3 103.4,2821.3 ; 103.4,3716.3 103.4,4214.72 290.7,4214.72 290.7,3716.3 103.4,3716.3 ; 103.4,4606.3 290.7,4606.3 290.7,5104.72 103.4,5104.72 103.4,4606.3 ; 103.4,5496.3 290.7,5496.3 290.7,5994.72 103.4,5994.72 103.4,5496.3 ; 103.4,6381.3 290.7,6381.3 290.7,6879.72 103.4,6879.72 103.4,6381.3 ; 416.78,152.76 604.08,152.76 604.08,651.18 416.78,651.18 416.78,152.76 ; 416.78,1042.76 416.78,1541.18 604.08,1541.18 604.08,1042.76 416.78,1042.76 ; 416.78,1932.76 416.78,2431.18 604.08,2431.18 604.08,1932.76 416.78,1932.76 ; 416.78,2817.76 416.78,3316.18 604.08,3316.18 604.08,2817.76 416.78,2817.76 ; 416.78,3712.76 416.78,4211.18 604.08,4211.18 604.08,3712.76 416.78,3712.76 ; 416.78,4602.76 604.08,4602.76 604.08,5101.18 416.78,5101.18 416.78,4602.76 ; 416.78,5492.76 604.08,5492.76 604.08,5991.18 416.78,5991.18 416.78,5492.76 ; 416.78,6377.76 604.08,6377.76 604.08,6876.18 416.78,6876.18 416.78,6377.76
Drill Drawing:
  lines w1: 42.78,-3.1 42.8,-3.1 ; 42.78,886.9 42.8,886.9 ; 42.78,1776.9 42.8,1776.9 ; 42.78,2661.9 42.8,2661.9 ; 42.78,3556.9 42.8,3556.9 ; 42.78,4446.9 42.8,4446.9 ; 42.78,5336.9 42.8,5336.9 ; 42.78,6221.9 42.8,6221.9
